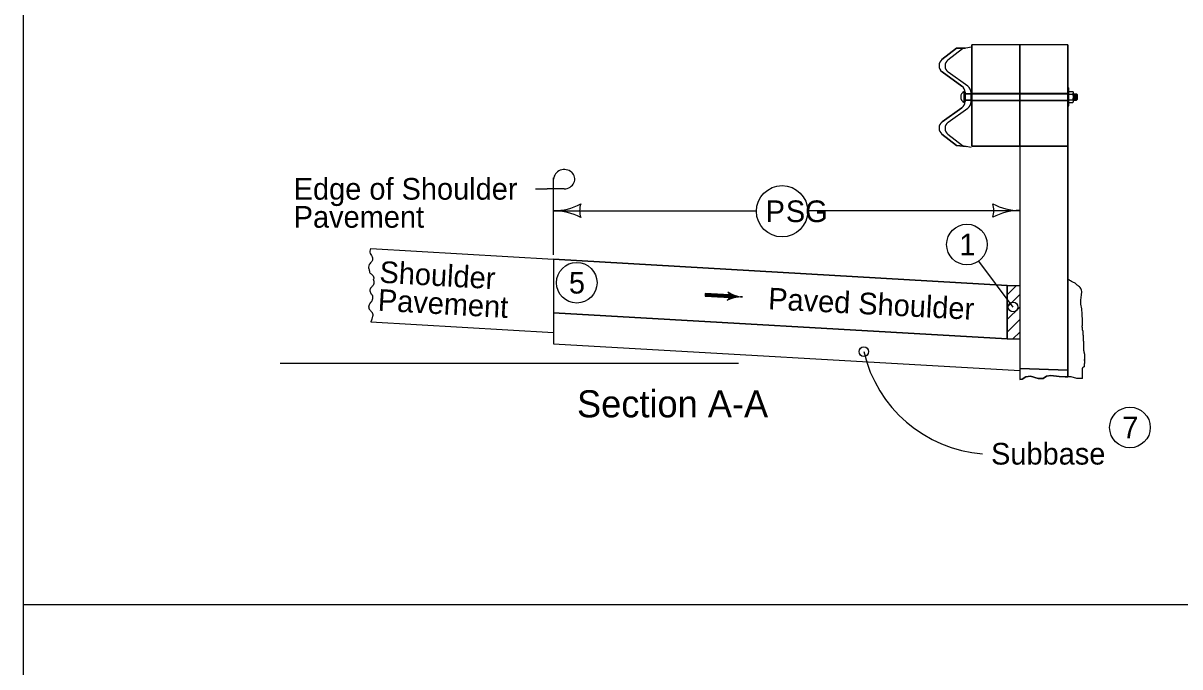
# Model space of a CAD drawing. Extents: x 10133 to 81668, y 7924 to 12229.
# Drawn here: x 10147 to 11002, y 11094 to 11570 of the extents above; entities that cross this region are included whole.
import ezdxf

# ---------------------------------------------------------------- set-up
doc = ezdxf.new("R2010")
doc.units = 0
for name, color, linetype in [('Cell', 7, 'Continuous'), ('dsnTextFinalPlan', 7, 'Continuous'), ('Level 1', 7, 'Continuous'), ('Level 12', 7, 'Continuous'), ('Level 21', 7, 'Continuous'), ('Level 4', 7, 'Continuous'), ('SheetText', 7, 'Continuous')]:
    doc.layers.add(name, color=color, linetype=linetype)

msp = doc.modelspace()

# ---------------------------------------------------------------- linework, layer by layer
at = {"layer": 'Cell'}
for p, q in [((10826.16, 11533.56), (10840.67, 11523.14)), ((10840.67, 11507.07), (10826.16, 11496.65)), ((10874.2, 11375.83), (10539.06, 11395.31)), ((10539.06, 11395.31), (10539.06, 11355.72)), ((10874.2, 11336.4), (10874.2, 11375.83)), ((10539.06, 11355.72), (10874.2, 11336.4))]:
    msp.add_line(p, q, dxfattribs=at)
for points in [[(10830.41, 11542.46), (10830.39, 11542.45), (10841.17, 11550.86), (10843.06, 11551.19), (10836.73, 11551.08), (10825.96, 11542.68)], [(10883.45, 11517.77), (10883.45, 11553.44), (10847.9, 11553.44), (10847.9, 11517.77), (10847.91, 11517.77), (10883.45, 11517.77)], [(10919, 11517.77), (10919, 11521.76), (10919, 11553.44), (10883.45, 11553.44), (10883.45, 11517.77), (10919, 11517.77)], [(10845.11, 11522.93), (10845.14, 11522.91), (10830.58, 11533.36), (10830.6, 11533.34)], [(10843.06, 11518.51), (10843.06, 11517.43), (10847.51, 11517.43), (10847.51, 11518.29), (10847.51, 11518.29)], [(10847.51, 11511.48), (10847.51, 11511.48), (10847.51, 11512.77), (10843.06, 11512.77), (10843.06, 11511.7), (10843.06, 11512.77), (10843.06, 11512.77), (10843.06, 11511.7)], [(10847.9, 11517.43), (10847.9, 11512.77), (10847.91, 11512.77), (10883.45, 11512.77), (10883.45, 11517.43), (10847.91, 11517.43), (10847.9, 11517.43)], [(10847.9, 11512.43), (10847.9, 11478.79), (10883.45, 11478.79), (10883.45, 11512.43), (10847.9, 11512.43)], [(10919, 11512.77), (10919, 11517.43), (10883.45, 11517.43), (10883.45, 11512.77), (10919, 11512.77)], [(10919, 11478.79), (10919, 11508.43), (10919, 11512.43), (10883.45, 11512.43), (10883.45, 11478.79), (10919, 11478.79)], [(10830.6, 11496.44), (10830.58, 11496.42), (10845.14, 11506.87), (10845.11, 11506.85)], [(10825.96, 11487.53), (10836.73, 11479.14), (10843.83, 11478.45), (10841.17, 11478.92), (10830.39, 11487.33), (10830.41, 11487.31)], [(10919, 11313.45), (10919, 11478.79), (10883.45, 11478.79), (10883.45, 11375.82), (10883.45, 11369.13), (10883.45, 11369.13), (10883.45, 11369.13), (10883.45, 11359.9), (10883.45, 11359.9), (10883.45, 11359.9), (10883.45, 11350.76), (10883.45, 11350.76), (10883.45, 11350.76), (10883.45, 11343.83), (10883.45, 11314.61), (10919, 11313.45)], [(10919, 11313.45), (10883.45, 11314.61), (10883.45, 11306.56), (10885.26, 11306.81), (10888.02, 11308.4), (10891.3, 11308.93), (10896.92, 11307.34), (10900.63, 11307.13), (10903.28, 11308.93), (10906.36, 11309.56), (10912.61, 11308.82), (10916.85, 11308.4), (10919, 11308.4), (10919, 11313.45)]]:
    msp.add_lwpolyline(points, dxfattribs=at)
msp.add_lwpolyline([(10847.51, 11517.43), (10843.06, 11517.43), (10843.06, 11513.97), (10843.06, 11515.11), (10843.06, 11512.77), (10847.51, 11512.77)], close=True, dxfattribs=at)
for centre, start, end in [((10829.44, 11538.19), 127.75002, 234.69086), ((10833.89, 11537.97), 127.75002, 234.69086), ((10837.39, 11518.51), 0, 54.69099), ((10841.83, 11518.29), 0, 54.69099), ((10837.39, 11511.7), 305.30901, 0), ((10841.83, 11511.48), 305.30901, 0), ((10829.44, 11492.02), 125.30914, 232.24998), ((10833.89, 11491.8), 125.30914, 232.24998)]:
    msp.add_arc(centre, 5.68, start, end, dxfattribs=at)
at = {"layer": 'dsnTextFinalPlan'}
for p, q in [((10825.96, 11542.68), (10836.73, 11551.08)), ((10830.39, 11542.45), (10841.17, 11550.86)), ((10836.73, 11551.08), (10843.06, 11551.19)), ((10841.17, 11550.86), (10847.51, 11551.98)), ((10919, 11553.44), (10847.9, 11553.44)), ((10847.9, 11478.79), (10847.9, 11553.44)), ((10883.45, 11478.79), (10883.45, 11553.44)), ((10919, 11553.44), (10919, 11308.4)), ((10840.67, 11523.14), (10826.16, 11533.56)), ((10845.14, 11522.91), (10830.58, 11533.36)), ((10919, 11521.74), (10919.68, 11521.74)), ((10919.68, 11508.4), (10919.68, 11521.74)), ((10842.29, 11511.04), (10842.29, 11519.12)), ((10842.29, 11517.43), (10847.72, 11517.43)), ((10842.29, 11512.77), (10847.9, 11512.77)), ((10843.06, 11511.7), (10843.06, 11518.51)), ((10843.06, 11511.7), (10843.06, 11515.11)), ((10843.06, 11515.11), (10843.06, 11511.7)), ((10843.24, 11517.43), (10847.9, 11517.43)), ((10847.51, 11514.89), (10847.51, 11518.29)), ((10847.51, 11511.48), (10847.51, 11514.89)), ((10847.51, 11514.89), (10847.51, 11511.48)), ((10847.9, 11512.43), (10919, 11512.43)), ((10847.91, 11517.77), (10919, 11517.77)), ((10847.91, 11517.43), (10919, 11517.43)), ((10847.91, 11512.77), (10919, 11512.77)), ((10919.68, 11519.11), (10922.64, 11519.11)), ((10919.68, 11517.09), (10922.64, 11517.09)), ((10919.68, 11513.05), (10922.64, 11513.05)), ((10923.01, 11512.04), (10923.01, 11518.1)), ((10923.01, 11517.4), (10925.38, 11517.4)), ((10923.01, 11512.74), (10925.38, 11512.74)), ((10923.9, 11517.4), (10923.9, 11512.74)), ((10924.64, 11517.4), (10924.64, 11512.74)), ((10925.38, 11517.4), (10925.83, 11516.87)), ((10925.38, 11517.4), (10925.38, 11512.74)), ((10925.83, 11513.27), (10925.38, 11512.74)), ((10925.83, 11516.87), (10925.83, 11513.27)), ((10826.16, 11496.65), (10840.67, 11507.07)), ((10830.58, 11496.42), (10845.14, 11506.87)), ((10919, 11508.4), (10919.68, 11508.4)), ((10919.68, 11511.03), (10922.64, 11511.03)), ((10836.73, 11479.14), (10825.96, 11487.53)), ((10841.17, 11478.92), (10830.39, 11487.33)), ((10843.83, 11478.45), (10836.73, 11479.14)), ((10847.51, 11477.8), (10841.17, 11478.92)), ((10883.45, 11478.79), (10847.9, 11478.79)), ((10883.45, 11478.79), (10883.45, 11306.56)), ((10403.92, 11403.17), (10539.06, 11395.31)), ((10539.06, 11395.31), (10539.06, 11341.3)), ((10539.06, 11395.31), (10874.2, 11375.83)), ((10874.2, 11369.08), (10880.94, 11375.83)), ((10874.2, 11369.08), (10880.94, 11375.83)), ((10874.2, 11369.08), (10880.94, 11375.83)), ((10874.2, 11369.08), (10880.94, 11375.83)), ((10874.2, 11375.83), (10883.43, 11375.83)), ((10874.2, 11375.83), (10874.2, 11336.4)), ((10874.2, 11359.9), (10883.43, 11369.13)), ((10874.2, 11359.9), (10883.43, 11369.13)), ((10874.2, 11359.9), (10883.43, 11369.13)), ((10874.2, 11359.9), (10883.43, 11369.13)), ((10929.05, 11369.06), (10929.05, 11369.06)), ((10874.2, 11350.67), (10883.43, 11359.91)), ((10874.2, 11350.67), (10883.43, 11359.91)), ((10874.2, 11350.67), (10883.43, 11359.91)), ((10874.2, 11350.67), (10883.43, 11359.91)), ((10403.95, 11349.16), (10539.06, 11341.3)), ((10874.2, 11336.4), (10539.06, 11355.72)), ((10874.2, 11341.44), (10883.43, 11350.68)), ((10539.06, 11341.3), (10539.06, 11332.88)), ((10878.29, 11336.4), (10883.43, 11341.54)), ((10539.06, 11332.88), (10883.45, 11313.02)), ((10874.2, 11336.4), (10883.43, 11336.4)), ((10337, 11318.47), (10675.51, 11318.47))]:
    msp.add_line(p, q, dxfattribs=at)
for points in [[(10923, 11512.36), (10922.95, 11512.63), (10922.9, 11512.8), (10922.82, 11512.96), (10922.7, 11513.05), (10922.78, 11513.15), (10922.86, 11513.37), (10922.92, 11513.68), (10923, 11514.43), (10923, 11512.36), (10922.98, 11512.5), (10922.93, 11512.72), (10922.86, 11512.93), (10922.74, 11513.04), (10922.78, 11513.13), (10922.84, 11513.28), (10922.94, 11513.78), (10922.98, 11514.16), (10922.98, 11512.55), (10922.95, 11512.67), (10922.9, 11512.84), (10922.78, 11513.04), (10922.83, 11513.21), (10922.91, 11513.54), (10922.96, 11513.87), (10922.96, 11512.71), (10922.92, 11512.84), (10922.81, 11513.03), (10922.85, 11513.25), (10922.9, 11513.5), (10922.94, 11513.68), (10922.94, 11512.81), (10922.88, 11512.92), (10922.83, 11513.03), (10922.92, 11513.49), (10922.92, 11512.89), (10922.85, 11513.03), (10922.9, 11513.32), (10922.9, 11512.97), (10922.86, 11513.04), (10922.88, 11513.14), (10922.88, 11513.06)], [(10922.71, 11517.09), (10922.78, 11517.14), (10922.85, 11517.24), (10922.94, 11517.46), (10922.99, 11517.75), (10923, 11515.8), (10922.94, 11516.31), (10922.89, 11516.68), (10922.77, 11517.01), (10922.71, 11517.09), (10922.76, 11517.1), (10922.87, 11517.25), (10922.96, 11517.47), (10922.98, 11517.63), (10922.98, 11516.09), (10922.91, 11516.58), (10922.85, 11516.85), (10922.75, 11517.07), (10922.78, 11517.08), (10922.92, 11517.3), (10922.96, 11517.45), (10922.96, 11516.35), (10922.77, 11517.06), (10922.94, 11517.34), (10922.94, 11516.48), (10922.79, 11517.05), (10922.92, 11517.27), (10922.92, 11516.63), (10922.81, 11517.03), (10922.9, 11517.2), (10922.9, 11516.79), (10922.83, 11517.01), (10922.89, 11517.13), (10922.89, 11516.93), (10922.86, 11517), (10922.87, 11517.05)], [(10929.52, 11345.22), (10929.46, 11344.94), (10929.46, 11344.75), (10929.46, 11344.55), (10929.46, 11344.36), (10929.46, 11344.16), (10929.46, 11343.97), (10929.46, 11343.67), (10929.46, 11343.48), (10929.56, 11343.19), (10929.66, 11342.89), (10929.85, 11342.7), (10929.85, 11342.5), (10929.95, 11342.31), (10929.95, 11342.11), (10929.95, 11341.92), (10930.05, 11341.82), (10930.05, 11341.62), (10930.05, 11341.43), (10930.05, 11341.23), (10930.05, 11341.04), (10930.05, 11340.84), (10930.05, 11340.55), (10930.05, 11340.26), (10930.05, 11340.06), (10930.05, 11339.77), (10930.05, 11339.57), (10930.05, 11339.38), (10930.14, 11339.28), (10930.14, 11339.08), (10930.14, 11338.89), (10930.14, 11338.69), (10930.14, 11338.5), (10930.14, 11338.3), (10930.14, 11338.11), (10930.14, 11337.91), (10930.14, 11337.71), (10930.14, 11337.52), (10930.14, 11337.32), (10930.14, 11337.13), (10930.14, 11336.93), (10930.14, 11336.74), (10930.14, 11336.54), (10930.14, 11336.35), (10930.14, 11336.15), (10930.14, 11335.96), (10930.14, 11335.76), (10930.24, 11335.66), (10930.24, 11335.47), (10930.24, 11335.27), (10930.34, 11335.17), (10930.34, 11334.98), (10930.34, 11334.78), (10930.44, 11334.69), (10930.44, 11334.49), (10930.44, 11334.3), (10930.44, 11334.1), (10930.44, 11333.81), (10930.53, 11333.51), (10930.53, 11333.32), (10930.53, 11333.12), (10930.53, 11332.93), (10930.53, 11332.73), (10930.53, 11332.54), (10930.53, 11332.34), (10930.53, 11332.15), (10930.53, 11331.95), (10930.53, 11331.75), (10930.53, 11331.56), (10930.53, 11331.36), (10930.53, 11331.17), (10930.53, 11330.97), (10930.53, 11330.78), (10930.53, 11330.58), (10930.53, 11330.39), (10930.53, 11330.19), (10930.53, 11330), (10930.53, 11329.8), (10930.53, 11329.61), (10930.53, 11329.41), (10930.53, 11329.21), (10930.53, 11329.02), (10930.53, 11328.82), (10930.53, 11328.63), (10930.53, 11328.43), (10930.53, 11328.24), (10930.53, 11328.04), (10930.53, 11327.85), (10930.63, 11327.75), (10930.63, 11327.46), (10930.63, 11327.26), (10930.73, 11327.06), (10930.83, 11326.77), (10930.83, 11326.58), (10930.93, 11326.48), (10930.93, 11326.28), (10931.02, 11326.19), (10931.12, 11326.09), (10931.12, 11325.89), (10931.12, 11325.7), (10931.12, 11325.5), (10931.22, 11325.4), (10931.22, 11325.21), (10931.22, 11325.01), (10931.22, 11324.82), (10931.22, 11324.62), (10931.22, 11324.43), (10931.22, 11324.23), (10931.22, 11324.04), (10931.22, 11323.84), (10931.22, 11323.65), (10931.22, 11323.45), (10931.22, 11323.25), (10931.22, 11323.06), (10931.22, 11322.86), (10931.22, 11322.67), (10931.22, 11322.47), (10931.22, 11322.28), (10931.22, 11322.08), (10931.22, 11321.89), (10931.22, 11321.69), (10931.22, 11321.5), (10931.22, 11321.3), (10931.22, 11321.1), (10931.22, 11320.91), (10931.22, 11320.71), (10931.22, 11320.52), (10931.22, 11320.52), (10931.22, 11320.81), (10931.22, 11321.01), (10931.22, 11321.2), (10931.22, 11321.01), (10931.22, 11320.81), (10931.22, 11320.62), (10931.22, 11320.42), (10931.22, 11320.23), (10931.22, 11320.03), (10931.22, 11319.83), (10931.22, 11319.64), (10931.22, 11319.44), (10931.22, 11319.25), (10931.22, 11319.05), (10931.22, 11318.86), (10931.22, 11318.66), (10931.22, 11318.47), (10931.22, 11318.27), (10931.12, 11318.17), (10931.12, 11317.98), (10931.12, 11317.78), (10931.12, 11317.59), (10931.12, 11317.39), (10931.12, 11317.2), (10931.12, 11317), (10931.12, 11316.81), (10931.12, 11316.61), (10931.12, 11316.42), (10931.12, 11316.22), (10931.02, 11316.12), (10930.93, 11315.93), (10930.83, 11315.83), (10930.73, 11315.73), (10930.63, 11315.63), (10930.44, 11315.54), (10930.24, 11315.54), (10930.14, 11315.44), (10930.05, 11315.34), (10929.95, 11315.24), (10929.75, 11315.14), (10929.66, 11315.05), (10929.66, 11314.85), (10929.56, 11314.75), (10929.56, 11314.56), (10929.56, 11314.36), (10929.56, 11314.17), (10929.56, 11307.35)], [(10929.69, 11307.35), (10925.54, 11307.23), (10921.41, 11308.4), (10916.85, 11308.4), (10912.61, 11308.82), (10906.36, 11309.56), (10903.28, 11308.93), (10900.63, 11307.13), (10896.92, 11307.34), (10891.3, 11308.93), (10888.02, 11308.4), (10885.26, 11306.81), (10883.45, 11306.56)]]:
    msp.add_lwpolyline(points, dxfattribs=at)
for centre, radius, start, end in [((10829.44, 11538.19), 5.68, 127.75002, 234.69086), ((10833.89, 11537.97), 5.68, 127.75002, 234.69086), ((10837.39, 11518.51), 5.68, 360, 54.69099), ((10841.83, 11518.29), 5.68, 360, 54.69099), ((10844.36, 11515.09), 4.54, 117.20289, 242.8461), ((10837.39, 11511.7), 5.68, 305.30901, 0), ((10841.83, 11511.48), 5.68, 305.30901, 0), ((10829.44, 11492.02), 5.68, 125.30914, 232.24998), ((10833.89, 11491.8), 5.68, 125.30914, 232.24998)]:
    msp.add_arc(centre, radius, start, end, dxfattribs=at)
for centre in [(10922.64, 11518.1), (10922.64, 11512.04)]:
    msp.add_ellipse(centre, major_axis=(0, -1.01), ratio=0.362258, start_param=6.283156, end_param=9.424748, dxfattribs=at)
for points in [[(10403.92, 11403.17), (10403.42, 11399.57), (10404.46, 11398.06), (10405.32, 11395.77), (10404.72, 11393.71), (10402.81, 11391.33), (10402.29, 11389.43), (10402.81, 11387.14), (10403.68, 11384.76), (10404.72, 11384.05), (10406.1, 11381.51), (10406.09, 11380.67)], [(10404.13, 11363.56), (10404.34, 11363.81), (10404.54, 11364.07), (10404.89, 11364.63), (10405.17, 11365.22), (10405.29, 11365.53), (10405.39, 11365.84), (10405.52, 11366.46), (10405.57, 11367.08), (10405.53, 11367.67), (10405.47, 11367.95), (10405.43, 11368.08), (10405.38, 11368.21), (10405.17, 11368.59), (10404.89, 11368.95), (10404.59, 11369.32), (10404.34, 11369.72), (10404.2, 11370), (10404.06, 11370.28), (10403.8, 11370.86), (10403.6, 11371.42), (10403.53, 11371.72), (10403.47, 11372.01), (10403.47, 11372.14), (10403.46, 11372.27), (10403.61, 11373.04), (10403.82, 11373.56), (10404.08, 11374.07), (10404.53, 11374.71), (10405.04, 11375.25), (10405.56, 11375.8), (10405.79, 11376.11), (10405.99, 11376.45), (10406.2, 11376.92), (10406.35, 11377.4), (10406.45, 11377.87), (10406.49, 11378.11), (10406.5, 11378.23), (10406.51, 11378.35), (10406.46, 11378.86), (10406.31, 11379.37), (10406.26, 11379.5), (10406.2, 11379.62), (10406.16, 11379.75), (10406.13, 11379.88), (10406.09, 11380.67)], [(10929.52, 11345.22), (10929.84, 11348.12), (10929.62, 11352.99), (10929.18, 11358.74), (10928.51, 11363.16), (10928.73, 11366.48), (10929.18, 11370.68), (10928.51, 11373.77), (10926.3, 11375.76), (10924.31, 11377.53), (10922.1, 11378.64), (10919.89, 11379.96), (10919, 11380.63)], [(10404.13, 11363.56), (10403.92, 11363.33), (10403.67, 11363.09), (10403.43, 11362.85), (10403.25, 11362.58), (10403.11, 11362.3), (10402.97, 11362.01), (10402.71, 11361.44), (10402.6, 11361.16), (10402.51, 11360.87), (10402.43, 11360.58), (10402.41, 11360.43), (10402.39, 11360.28), (10402.4, 11359.77), (10402.53, 11359.25), (10402.73, 11358.74), (10402.99, 11358.22), (10403.44, 11357.59), (10403.96, 11357.04), (10404.47, 11356.49), (10404.7, 11356.19), (10404.9, 11355.85), (10405.3, 11354.9), (10405.41, 11354.43), (10405.42, 11353.95), (10405.38, 11353.66), (10405.34, 11353.37), (10405.28, 11353.08), (10405.21, 11352.8), (10404.9, 11351.65), (10404.72, 11351.04), (10404.52, 11350.44), (10404.3, 11349.85), (10404.17, 11349.56), (10404.03, 11349.28), (10403.95, 11349.16)]]:
    msp.add_spline(points, degree=3, dxfattribs=at)
at = {"layer": 'Level 1'}
msp.add_line((10147.13, 12229.21), (10147.13, 10619.21), dxfattribs=at)
at = {"layer": 'Level 12'}
for centre, radius in [((10844.39, 11406.12), 15), ((10556.11, 11377.93), 15), ((10878.51, 11360), 3.58), ((10964.83, 11271.07), 15)]:
    msp.add_circle(centre, radius, dxfattribs=at)
at = {"layer": 'Level 21'}
msp.add_circle((10556.11, 11377.93), 15, dxfattribs=at)
at = {"layer": 'Level 4'}
for p, q in [((10878.51, 11360), (10853.13, 11393.93)), ((12302.71, 11140.21), (10147.13, 11140.21))]:
    msp.add_line(p, q, dxfattribs=at)
msp.add_circle((10768.2, 11327.04), 3.54, dxfattribs=at)
msp.add_circle((10768.2, 11327.04), 3.54, dxfattribs=at)
at = {"layer": 'SheetText'}
for p, q in [((10539.06, 11434.39), (10539.06, 11455.25)), ((10525.69, 11447.24), (10534.37, 11447.24)), ((10546.87, 11447.24), (10534.37, 11447.24)), ((10539.06, 11398.46), (10539.06, 11434.39)), ((10539.06, 11431.07), (10688.89, 11431.07)), ((10726.74, 11431.23), (10883.45, 11431.23)), ((10669.26, 11367.97), (10651.06, 11369.02)), ((10669.16, 11367.03), (10669.16, 11367.03)), ((10669.28, 11368.97), (10669.28, 11368.97))]:
    msp.add_line(p, q, dxfattribs=at)
for points in [[(10669.29, 11368.91), (10651.12, 11369.96), (10650.99, 11368.08), (10669.16, 11367.03), (10669.22, 11368.64), (10651.34, 11369.74), (10651.29, 11368.24), (10668.78, 11367.29), (10668.9, 11368.41), (10651.58, 11369.47), (10651.55, 11368.47), (10668.57, 11367.49), (10668.66, 11368.19), (10651.77, 11369.25), (10651.75, 11368.69), (10668.36, 11367.75)], [(10668.89, 11370.16), (10669.58, 11369), (10669.56, 11367.35), (10668.8, 11365.95), (10671.56, 11366.82), (10674.75, 11367.47), (10675.65, 11367.6), (10673.41, 11368.15), (10670.18, 11369.38), (10669.23, 11369.91), (10669.36, 11366.4), (10674.3, 11367.62), (10669.67, 11369.2), (10669.68, 11366.78), (10673.08, 11367.71), (10670.08, 11368.57), (10669.85, 11367.19), (10672, 11367.69), (10670.42, 11368.2), (10670.28, 11367.54), (10671.07, 11367.7)]]:
    msp.add_lwpolyline(points, dxfattribs=at)
msp.add_circle((10707.82, 11430.67), 18.93, dxfattribs=at)
for centre, radius, start, end in [((10539.06, 11473.57), 42.5, 270, 298.07249), ((10574.7, 11431.07), 16.42, 162.26665, 197.73335), ((10847.82, 11431.23), 16.42, 342.26665, 17.73335), ((10883.45, 11473.73), 42.5, 241.92751, 270), ((10539.06, 11388.57), 42.5, 61.92751, 90), ((10883.45, 11388.73), 42.5, 90, 118.07249), ((10863.43, 11349.16), 97.76, 193.07698, 265.55799)]:
    msp.add_arc(centre, radius, start, end, dxfattribs=at)
for centre, major_axis, start_param, end_param in [((10546.87, 11454.38), (-7.81, 0), 1.570796, 6.283185), ((10665.5, 11368.18), (3.88, 0), 5.202895, 7.237436), ((10677.77, 11347.19), (22.17, 0), 1.537172, 2.061295), ((10680.56, 11387.61), (-22.17, 0), 0.954258, 1.478381)]:
    msp.add_ellipse(centre, major_axis=major_axis, ratio=0.913811, start_param=start_param, end_param=end_param, dxfattribs=at)

# ---------------------------------------------------------------- texts
at = {"layer": 'Level 12'}
for s, p in [('1', (10838.77, 11398.12)), ('5', (10550.34, 11369.93)), ('7', (10959.13, 11263.07))]:
    msp.add_text(s, height=16, dxfattribs=at).set_placement(p)
at = {"layer": 'SheetText'}
for s, height, p in [('Edge of Shoulder ', 16, (10347, 11439.24)), ('Pavement', 16, (10347, 11418.53)), ('P', 16, (10695.69, 11422.67)), ('SG', 16, (10710.61, 11422.67)), ('Section A-A', 20, (10556.32, 11278.54)), ('Subbase', 16, (10862.21, 11243.69))]:
    msp.add_text(s, height=height, dxfattribs=at).set_placement(p)
for s, rotation, p in [('Shoulder', 356.73462, (10410.05, 11378)), ('Pavement', 356.73462, (10408.87, 11357.33)), ('Paved Shoulder ', 357.0678, (10697.28, 11358.33))]:
    msp.add_text(s, height=16, rotation=rotation, dxfattribs=at).set_placement(p)

doc.saveas('drawing.dxf')
